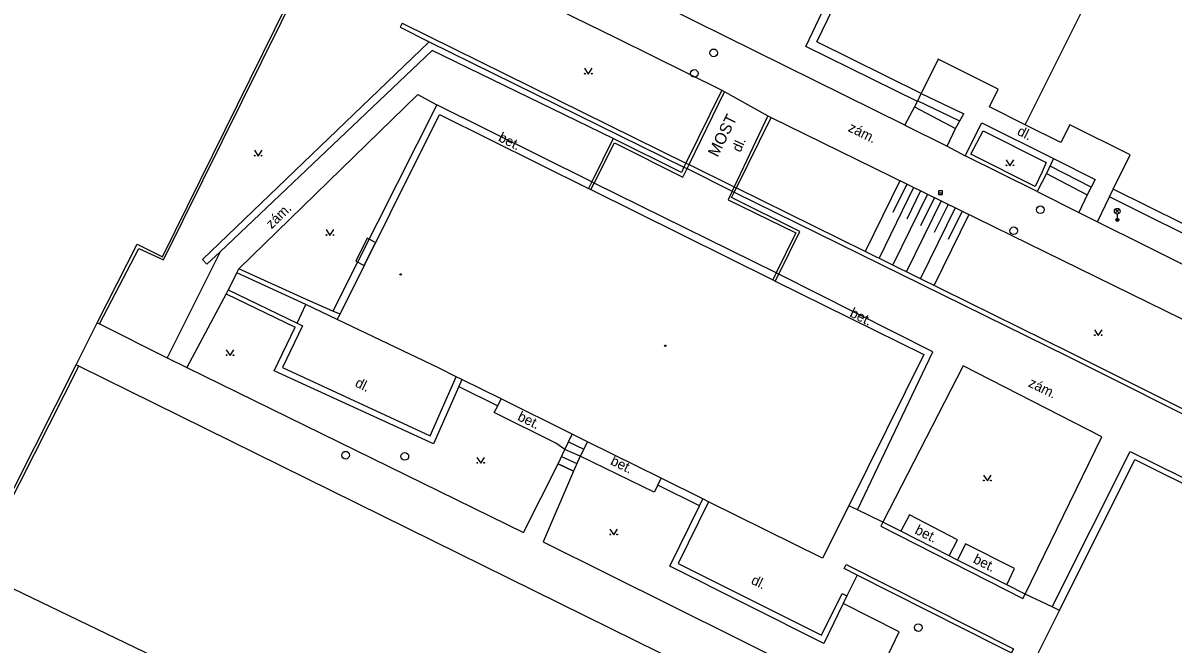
# Model space of a CAD drawing. Extents: x -602419 to -601554, y -1162937 to -1162362.
# Drawn here: x -602253.1 to -602178.2, y -1162478.5 to -1162438 of the extents above; entities that cross this region are included whole.
import ezdxf

# ---------------------------------------------------------------- set-up
doc = ezdxf.new("R2010")
doc.units = 0
doc.layers.add('Podklad', color=7, linetype='Continuous')

msp = doc.modelspace()

# ---------------------------------------------------------------- linework, layer by layer
at = {"layer": 'Podklad'}
for p, q in [((-602193.515, -1162449.09), (-602193.265, -1162449.09)), ((-602182.0125, -1162450.43), (-602181.7475, -1162450.165)), ((-602182.0125, -1162450.165), (-602181.7475, -1162450.43)), ((-602181.88, -1162450.485), (-602181.88, -1162450.86))]:
    msp.add_line(p, q, dxfattribs=at)
for points in [[(-602248.17, -1162457.64), (-602245.6, -1162452.7199), (-602244, -1162453.4699), (-602232.4699, -1162430.19)], [(-602244.07, -1162453.27), (-602232.65, -1162430.1)], [(-602230.2199, -1162431.31), (-602214.51, -1162439.01), (-602207.64, -1162442.42)], [(-602187.88, -1162444.6599), (-602182.35, -1162433.58)], [(-602194.9, -1162443.15), (-602202.1599, -1162439.56), (-602201.1, -1162437.32), (-602204.06, -1162435.75), (-602204.69, -1162436.93), (-602208.09, -1162435.27), (-602207.53, -1162434.12)], [(-602195.7199, -1162444.7), (-602213.32, -1162435.9699)], [(-602201.45, -1162439.26), (-602200.35, -1162437.02)], [(-602228.46, -1162438.04), (-602228.59, -1162438.31), (-602226.7, -1162439.27)], [(-602228.46, -1162438.04), (-602209.9699, -1162447.1599)], [(-602241.45, -1162453.45), (-602226.7, -1162439.27)], [(-602226.49, -1162439.83), (-602240.31, -1162452.94)], [(-602226.7, -1162439.27), (-602210.1, -1162447.42)], [(-602214.7199, -1162445.56), (-602226.49, -1162439.83)], [(-602194.65, -1162442.63), (-602201.45, -1162439.26)], [(-602193.54, -1162440.39), (-602194.65, -1162442.63)], [(-602189.63, -1162442.34), (-602193.54, -1162440.39)], [(-602216.58, -1162440.985), (-602216.33, -1162441.36), (-602216.08, -1162440.985)], [(-602239.09, -1162454.05), (-602227.44, -1162442.7), (-602226.2, -1162443.37)], [(-602207.64, -1162442.42), (-602209.9699, -1162447.1599)], [(-602209.77, -1162447.26), (-602207.45, -1162442.52)], [(-602207.64, -1162442.42), (-602204.63, -1162444.08), (-602204.4099, -1162444.2)], [(-602194.9, -1162443.15), (-602194.65, -1162442.63)], [(-602194.65, -1162442.63), (-602191.87, -1162443.96)], [(-602190.21, -1162443.5), (-602189.63, -1162442.34)], [(-602226.2, -1162443.37), (-602231.37, -1162453.61)], [(-602216.1, -1162448.39), (-602226.2, -1162443.37)], [(-602195.7199, -1162444.7), (-602194.9, -1162443.15)], [(-602195.09, -1162443.5), (-602192.4099, -1162444.9099)], [(-602192.14, -1162444.43), (-602194.88, -1162443.11)], [(-602187.88, -1162444.6599), (-602190.21, -1162443.5)], [(-602229.23, -1162450.44), (-602226.02, -1162444)], [(-602226.02, -1162444), (-602216.31, -1162448.82)], [(-602204.63, -1162444.08), (-602206.83, -1162448.7)], [(-602206.68, -1162448.77), (-602204.4099, -1162444.2)], [(-602204.4099, -1162444.2), (-602174.32, -1162458.96)], [(-602192.4099, -1162444.9099), (-602191.87, -1162443.96)], [(-602195.7199, -1162444.7), (-602192.95, -1162446.05)], [(-602192.95, -1162446.05), (-602192.4099, -1162444.9099)], [(-602191.78, -1162446.68), (-602190.71, -1162444.53)], [(-602191.4099, -1162446.58), (-602190.61, -1162445.06), (-602186.52, -1162447.12), (-602186.77, -1162447.73), (-602187.23, -1162448.69), (-602191.4099, -1162446.58)], [(-602190.71, -1162444.53), (-602186.03, -1162446.87)], [(-602185.55, -1162445.82), (-602187.88, -1162444.6599)], [(-602184.9699, -1162444.6599), (-602185.55, -1162445.82)], [(-602181.03, -1162446.62), (-602184.9699, -1162444.6599)], [(-602214.7199, -1162445.56), (-602216.1, -1162448.39)], [(-602215.95, -1162448.46), (-602214.63, -1162445.84), (-602210.17, -1162448.08), (-602209.9, -1162447.52)], [(-602210.1, -1162447.42), (-602210.27, -1162447.77), (-602214.7199, -1162445.56)], [(-602238.08, -1162446.325), (-602237.83, -1162446.7), (-602237.58, -1162446.325)], [(-602192.95, -1162446.05), (-602191.78, -1162446.68)], [(-602187.09, -1162449.01), (-602191.78, -1162446.68)], [(-602182.14, -1162448.86), (-602181.03, -1162446.62)], [(-602209.9699, -1162447.1599), (-602210.1, -1162447.42)], [(-602210.1, -1162447.42), (-602209.9, -1162447.52)], [(-602209.9699, -1162447.1599), (-602209.77, -1162447.26)], [(-602209.9, -1162447.52), (-602209.77, -1162447.26)], [(-602209.77, -1162447.26), (-602206.83, -1162448.7)], [(-602189.12, -1162446.955), (-602188.87, -1162447.33), (-602188.62, -1162446.955)], [(-602186.03, -1162446.87), (-602186.49, -1162447.85)], [(-602183.57, -1162448.7199), (-602186.26, -1162447.36)], [(-602186.03, -1162446.87), (-602183.31, -1162448.2199)], [(-602209.9, -1162447.52), (-602206.96, -1162448.98)], [(-602186.49, -1162447.85), (-602187.09, -1162449.01)], [(-602186.49, -1162447.85), (-602183.84, -1162449.24)], [(-602183.31, -1162448.2199), (-602183.84, -1162449.24)], [(-602216.1, -1162448.39), (-602216.31, -1162448.82)], [(-602216.31, -1162448.82), (-602216.17, -1162448.89)], [(-602216.17, -1162448.89), (-602215.95, -1162448.46)], [(-602216.17, -1162448.89), (-602204.31, -1162454.77)], [(-602215.95, -1162448.46), (-602216.1, -1162448.39)], [(-602204.09, -1162454.32), (-602215.95, -1162448.46)], [(-602206.96, -1162448.98), (-602207.23, -1162449.56), (-602202.82, -1162451.7), (-602204.09, -1162454.32)], [(-602206.83, -1162448.7), (-602206.96, -1162448.98)], [(-602206.96, -1162448.98), (-602206.82, -1162449.05)], [(-602206.83, -1162448.7), (-602206.68, -1162448.77)], [(-602206.82, -1162449.05), (-602206.68, -1162448.77)], [(-602206.68, -1162448.77), (-602184.94, -1162459.49), (-602164.7, -1162469.63)], [(-602196.03, -1162448.31), (-602198.29, -1162452.9099)], [(-602195.14, -1162448.75), (-602197.39, -1162453.35)], [(-602195.59, -1162448.53), (-602196.49, -1162450.37)], [(-602194.69, -1162448.9699), (-602195.59, -1162450.81)], [(-602182.39, -1162449.35), (-602182.14, -1162448.86)], [(-602175.31, -1162452.25), (-602182.14, -1162448.86)], [(-602203.93, -1162454.4), (-602202.56, -1162451.61), (-602207, -1162449.4099), (-602206.82, -1162449.05)], [(-602206.82, -1162449.05), (-602185.08, -1162459.76), (-602164.84, -1162469.9)], [(-602194.24, -1162449.19), (-602196.5, -1162453.79)], [(-602193.34, -1162449.63), (-602195.6, -1162454.23)], [(-602193.79, -1162449.4099), (-602194.69, -1162451.25)], [(-602187.09, -1162449.01), (-602184.38, -1162450.38)], [(-602183.84, -1162449.24), (-602184.38, -1162450.38)], [(-602183.1599, -1162450.99), (-602182.39, -1162449.35)], [(-602155.89, -1162462.54), (-602163.15, -1162458.94), (-602162.06, -1162456.7199), (-602165.09, -1162455.2), (-602165.64, -1162456.37), (-602168.63, -1162454.86), (-602171.58, -1162453.42), (-602171.02, -1162452.28), (-602173.99, -1162450.69), (-602175.15, -1162452.9699), (-602182.39, -1162449.35)], [(-602232.5, -1162457), (-602229.23, -1162450.44)], [(-602192.44, -1162450.07), (-602194.7, -1162454.68)], [(-602192.89, -1162449.85), (-602193.8, -1162451.69)], [(-602191.99, -1162450.29), (-602192.9, -1162452.13)], [(-602184.38, -1162450.38), (-602183.1599, -1162450.99)], [(-602191.55, -1162450.51), (-602193.81, -1162455.12)], [(-602183.1599, -1162450.99), (-602180.15, -1162452.49)], [(-602233.4099, -1162451.495), (-602233.1599, -1162451.87), (-602232.9099, -1162451.495)], [(-602248.31, -1162457.57), (-602245.7199, -1162452.44)], [(-602245.7199, -1162452.44), (-602244.07, -1162453.27)], [(-602230.92, -1162453.83), (-602230.18, -1162452.34), (-602230.74, -1162452.06), (-602231.48, -1162453.56), (-602230.92, -1162453.83)], [(-602180.15, -1162452.49), (-602173.75, -1162455.68)], [(-602240.31, -1162452.94), (-602243.76, -1162459.84)], [(-602241.17, -1162453.75), (-602241.45, -1162453.45)], [(-602240.31, -1162452.94), (-602241.17, -1162453.75)], [(-602239.21, -1162454.32), (-602239.09, -1162454.05)], [(-602232.96, -1162456.8), (-602234.6, -1162456.1), (-602239.09, -1162454.05)], [(-602231.37, -1162453.61), (-602232.96, -1162456.8)], [(-602239.21, -1162454.32), (-602239.78, -1162455.4099)], [(-602234.7199, -1162456.38), (-602239.21, -1162454.32)], [(-602204.09, -1162454.32), (-602204.31, -1162454.77)], [(-602204.31, -1162454.77), (-602204.15, -1162454.85)], [(-602204.15, -1162454.85), (-602203.93, -1162454.4)], [(-602204.15, -1162454.85), (-602194.48, -1162459.64)], [(-602203.93, -1162454.4), (-602204.09, -1162454.32)], [(-602198.8, -1162469.76), (-602193.9, -1162459.45), (-602203.93, -1162454.4)], [(-602239.92, -1162455.68), (-602242.48, -1162460.48)], [(-602239.78, -1162455.4099), (-602239.92, -1162455.68)], [(-602239.92, -1162455.68), (-602235.43, -1162457.86)], [(-602239.78, -1162455.4099), (-602235.3, -1162457.59)], [(-602235.3, -1162457.59), (-602234.7199, -1162456.38)], [(-602232.68, -1162457.35), (-602234.7199, -1162456.38)], [(-602232.5, -1162457), (-602232.96, -1162456.8)], [(-602232.68, -1162457.35), (-602232.5, -1162457)], [(-602249.68, -1162460.3), (-602248.31, -1162457.57)], [(-602248.31, -1162457.57), (-602248.17, -1162457.64)], [(-602248.17, -1162457.64), (-602243.76, -1162459.84)], [(-602224.77, -1162461.71), (-602226.42, -1162465.46), (-602236.78, -1162460.69), (-602235.43, -1162457.86)], [(-602235.3, -1162457.59), (-602234.94, -1162457.76), (-602236.25, -1162460.4699), (-602226.62, -1162464.93), (-602224.93, -1162461.08)], [(-602226.04, -1162460.53), (-602232.68, -1162457.35)], [(-602183.37, -1162458.025), (-602183.12, -1162458.4), (-602182.87, -1162458.025)], [(-602239.9099, -1162459.325), (-602239.6599, -1162459.7), (-602239.4099, -1162459.325)], [(-602243.76, -1162459.84), (-602242.48, -1162460.48)], [(-602194.48, -1162459.64), (-602199.37, -1162469.48)], [(-602256.42, -1162473.62), (-602249.68, -1162460.3)], [(-602256.26, -1162473.7), (-602249.5, -1162460.39)], [(-602249.5, -1162460.39), (-602249.68, -1162460.3)], [(-602089.26, -1162539.4), (-602108.58, -1162530.12), (-602154.26, -1162507.48), (-602198.48, -1162485.59), (-602249.5, -1162460.39)], [(-602242.48, -1162460.48), (-602220.55, -1162471.2199), (-602218.3, -1162466.75), (-602217.85, -1162465.81)], [(-602224.93, -1162461.08), (-602226.04, -1162460.53)], [(-602187.88, -1162475.25), (-602182.89, -1162464.99), (-602191.92, -1162460.36), (-602197.15, -1162470.55)], [(-602224.57, -1162461.26), (-602224.93, -1162461.08)], [(-602224.57, -1162461.26), (-602224.77, -1162461.71)], [(-602224.77, -1162461.71), (-602222.23, -1162462.9699)], [(-602222.01, -1162462.52), (-602224.57, -1162461.26)], [(-602222.45, -1162463.4099), (-602222.23, -1162462.9699)], [(-602222.23, -1162462.9699), (-602222.01, -1162462.52)], [(-602217.37, -1162464.82), (-602222.01, -1162462.52)], [(-602218.44, -1162465.4), (-602222.45, -1162463.4099)], [(-602217.85, -1162465.81), (-602218.44, -1162465.4)], [(-602217.85, -1162465.81), (-602217.37, -1162464.82)], [(-602217.61, -1162465.32), (-602216.62, -1162465.79)], [(-602216.38, -1162465.32), (-602217.37, -1162464.82)], [(-602216.38, -1162465.32), (-602216.85, -1162466.26)], [(-602211.59, -1162467.69), (-602216.38, -1162465.32)], [(-602216.85, -1162466.26), (-602217.85, -1162465.81)], [(-602186.13, -1162476.07), (-602181.04, -1162465.96), (-602170.96, -1162470.93)], [(-602223.58, -1162466.335), (-602223.33, -1162466.71), (-602223.08, -1162466.335)], [(-602216.85, -1162466.26), (-602217.3, -1162467.2199), (-602219.27, -1162471.84), (-602198.27, -1162482.28), (-602196.08, -1162477.7), (-602199.73, -1162475.86)], [(-602218.3, -1162466.75), (-602217.3, -1162467.2199)], [(-602217.3, -1162467.2199), (-602218.3, -1162466.75)], [(-602218.08, -1162466.28), (-602217.08, -1162466.74)], [(-602211.81, -1162468.14), (-602212.04, -1162468.6), (-602216.85, -1162466.26)], [(-602185.64, -1162476.31), (-602180.73, -1162466.4699)], [(-602180.73, -1162466.4699), (-602175.98, -1162468.84)], [(-602211.81, -1162468.14), (-602211.59, -1162467.69)], [(-602208.86, -1162469.04), (-602211.59, -1162467.69)], [(-602190.59, -1162467.495), (-602190.34, -1162467.87), (-602190.09, -1162467.495)], [(-602209.08, -1162469.49), (-602211.81, -1162468.14)], [(-602209.08, -1162469.49), (-602208.86, -1162469.04)], [(-602208.5, -1162469.2199), (-602208.86, -1162469.04)], [(-602211.03, -1162473.43), (-602209.08, -1162469.49)], [(-602208.5, -1162469.2199), (-602210.48, -1162473.24), (-602201.14, -1162477.92), (-602199.79, -1162475.21), (-602199.49, -1162475.36)], [(-602201.08, -1162472.9), (-602208.5, -1162469.2199)], [(-602199.37, -1162469.48), (-602201.08, -1162472.9)], [(-602198.8, -1162469.76), (-602199.37, -1162469.48)], [(-602197.15, -1162470.55), (-602198.8, -1162469.76)], [(-602197.15, -1162470.55), (-602197.28, -1162470.82), (-602188.02, -1162475.52), (-602187.88, -1162475.25)], [(-602195.9699, -1162471.15), (-602197.15, -1162470.55)], [(-602192.82, -1162472.75), (-602192.29, -1162471.71), (-602195.4099, -1162470.07), (-602195.9699, -1162471.15)], [(-602214.92, -1162471.005), (-602214.67, -1162471.38), (-602214.42, -1162471.005)], [(-602192.82, -1162472.75), (-602195.9699, -1162471.15)], [(-602189.08, -1162474.64), (-602188.57, -1162473.58), (-602191.76, -1162471.96), (-602192.29, -1162473.02)], [(-602192.29, -1162473.02), (-602192.82, -1162472.75)], [(-602256.26, -1162473.7), (-602209.38, -1162496.3)], [(-602200.98, -1162478.45), (-602211.03, -1162473.43)], [(-602198.81, -1162474.01), (-602199.6599, -1162473.58), (-602199.53, -1162473.31), (-602188.64, -1162478.8), (-602188.79, -1162479.06), (-602189.62, -1162478.65)], [(-602189.08, -1162474.64), (-602192.29, -1162473.02)], [(-602198.81, -1162474.01), (-602199.49, -1162475.36)], [(-602189.62, -1162478.65), (-602198.81, -1162474.01)], [(-602187.88, -1162475.25), (-602189.08, -1162474.64)], [(-602199.73, -1162475.86), (-602200.98, -1162478.45)], [(-602199.49, -1162475.36), (-602199.73, -1162475.86)], [(-602186.13, -1162476.07), (-602187.88, -1162475.25)], [(-602187.35, -1162479.73), (-602185.64, -1162476.31)], [(-602185.64, -1162476.31), (-602186.13, -1162476.07)]]:
    msp.add_lwpolyline(points, dxfattribs=at)
msp.add_lwpolyline([(-602193.515, -1162449.215), (-602193.265, -1162449.215), (-602193.265, -1162448.965), (-602193.515, -1162448.965)], close=True, dxfattribs=at)
for centre, radius in [((-602208.1599, -1162439.98), 0.25), ((-602216.5551, -1162441.3349), 0.025), ((-602216.1054, -1162441.3349), 0.025), ((-602209.43, -1162441.32), 0.25), ((-602238.0551, -1162446.6749), 0.025), ((-602237.6054, -1162446.6749), 0.025), ((-602189.0951, -1162447.3049), 0.025), ((-602188.6454, -1162447.3049), 0.025), ((-602186.89, -1162450.2), 0.25), ((-602181.88, -1162450.2975), 0.1875), ((-602181.88, -1162450.86), 0.1), ((-602181.88, -1162450.86), 0.0723), ((-602181.88, -1162450.86), 0.0438), ((-602233.385, -1162451.8449), 0.025), ((-602232.9353, -1162451.8449), 0.025), ((-602188.62, -1162451.57), 0.25), ((-602228.55, -1162454.4099), 0.045), ((-602228.55, -1162454.4099), 0.0199), ((-602183.3451, -1162458.3749), 0.025), ((-602182.8954, -1162458.3749), 0.025), ((-602211.32, -1162459.06), 0.045), ((-602211.32, -1162459.06), 0.0199), ((-602239.885, -1162459.6749), 0.025), ((-602239.4353, -1162459.6749), 0.025), ((-602232.14, -1162466.19), 0.25), ((-602228.28, -1162466.27), 0.25), ((-602223.5551, -1162466.6849), 0.025), ((-602223.1054, -1162466.6849), 0.025), ((-602190.5651, -1162467.8449), 0.025), ((-602190.1154, -1162467.8449), 0.025), ((-602214.8951, -1162471.3549), 0.025), ((-602214.4454, -1162471.3549), 0.025), ((-602194.84, -1162477.42), 0.25)]:
    msp.add_circle(centre, radius, dxfattribs=at)

# ---------------------------------------------------------------- texts
for s, height, rotation, p in [('MOST', 0.75, 63.56, (-602207.9099, -1162446.82)), ('bet.', 0.65, 333.47, (-602222.24, -1162445.7)), (' zám.', 0.65, 333.87, (-602199.68, -1162444.95)), ('dl.', 0.65, 333.43, (-602188.45, -1162445.29)), ('dl.', 0.65, 65.64, (-602206.42, -1162446.5)), (' zám.', 0.65, 44.25, (-602237.13, -1162451.65)), ('bet.', 0.65, 333.47, (-602199.35, -1162457.13)), ('dl.', 0.65, 333.64, (-602231.57, -1162461.68)), (' zám.', 0.65, 333.64, (-602187.94, -1162461.58)), ('bet.', 0.65, 334.06, (-602220.99, -1162463.88)), ('bet.', 0.65, 334.06, (-602214.94, -1162466.77)), ('bet.', 0.65, 333.58, (-602195.11, -1162471.27)), ('bet.', 0.65, 333.58, (-602191.32, -1162473.17)), ('dl.', 0.65, 333.64, (-602205.78, -1162474.54))]:
    msp.add_text(s, height=height, rotation=rotation, dxfattribs=at).set_placement(p)

doc.saveas('drawing.dxf')
